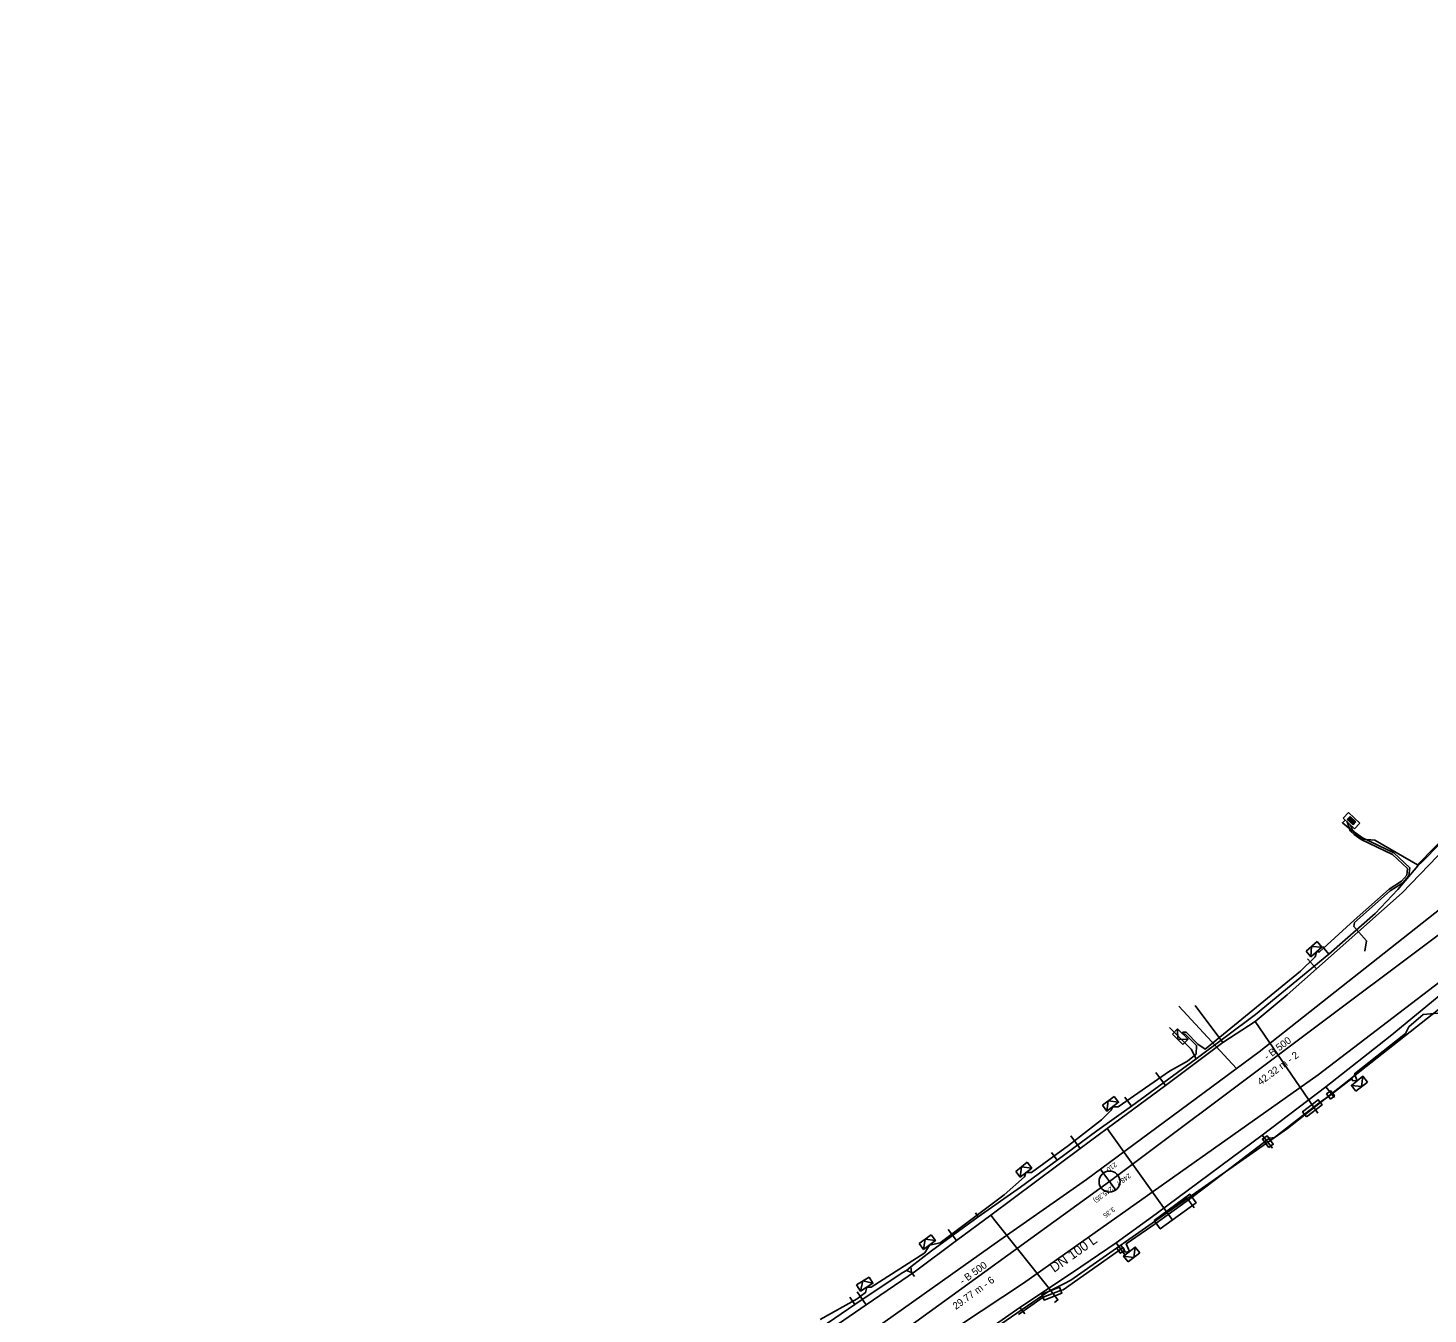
# Model space of a CAD drawing. Extents: x -600636 to -600148, y -1203980 to -1203569.
# Drawn here: x -600589.5 to -600456.1, y -1203740.1 to -1203617.6 of the extents above; entities that cross this region are included whole.
import ezdxf

# ---------------------------------------------------------------- set-up
doc = ezdxf.new("R2010")
doc.units = 0
for name, color, linetype in [('Cetin zam průběh', 7, 'Continuous'), ('EON objekty', 7, 'Continuous'), ('EON podzemní NN', 7, 'Continuous'), ('EON podzemní zrušené', 7, 'Continuous'), ('GasNet NTL', 7, 'Continuous'), ('Implicitní', 7, 'Continuous'), ('VaK Břeclav_kanalizace', 7, 'Continuous'), ('VaK Břeclav_kanalizace_popis', 7, 'Continuous'), ('Vak Břeclav_vodovod', 7, 'Continuous'), ('Vak Břeclav_vodovod_popis', 7, 'Continuous'), ('Vrstva 9', 7, 'Continuous')]:
    doc.layers.add(name, color=color, linetype=linetype)

# ---------------------------------------------------------------- blocks, each defined once
blk = doc.blocks.new('NN630')
at = {"layer": 'Vrstva 9'}
for points in [[(0, -0.7), (-0.7, 0)], [(-0.7, -0.7), (-0.7, 0), (0.7, 0), (0.7, -0.7)], [(-0.7, -0.7), (0.7, -0.7)], [(0, -0.7), (0.7, 0)]]:
    blk.add_lwpolyline(points, dxfattribs=at)
blk = doc.blocks.new('NN620')
at = {"layer": 'EON objekty'}
for points in [[(0.75, 0), (-0.75, 0)], [(-0.75, 0), (-0.75, -0.75)], [(0.75, -0.75), (0.75, 0)], [(-0.75, -0.75), (0.75, -0.75)], [(0.37, -0.18), (-0.38, -0.18)], [(-0.38, -0.18), (-0.38, -0.56)], [(-0.38, -0.56), (0.37, -0.56)], [(0.32, -0.23), (-0.33, -0.23)], [(-0.33, -0.23), (-0.33, -0.51)], [(-0.33, -0.51), (0.32, -0.51)], [(0.27, -0.27), (-0.28, -0.27)], [(-0.28, -0.27), (-0.28, -0.46)], [(-0.28, -0.46), (0.27, -0.46)], [(0.23, -0.32), (-0.23, -0.32)], [(-0.23, -0.32), (-0.23, -0.42)], [(-0.23, -0.42), (0.23, -0.42)], [(-0.19, -0.37), (0.19, -0.37)], [(0.23, -0.42), (0.23, -0.32)], [(0.27, -0.46), (0.27, -0.27)], [(0.32, -0.51), (0.32, -0.23)], [(0.37, -0.56), (0.37, -0.18)]]:
    blk.add_lwpolyline(points, dxfattribs=at)
blk = doc.blocks.new('MoSymbol 2')
at = {"layer": 'Implicitní'}
blk.add_line((0, 0.0005), (0, -0.00075), dxfattribs=at)
blk.add_circle((0, 0), 0.0005, dxfattribs=at)

msp = doc.modelspace()

# ---------------------------------------------------------------- linework, layer by layer
at = {"layer": 'Cetin zam průběh'}
for points in [[(-600456.63, -1203697.04), (-600445.32, -1203685.49)], [(-600456.63, -1203697.04), (-600457.08, -1203697.43), (-600458.99, -1203699.7), (-600461.15, -1203701.99), (-600465.55, -1203705.86), (-600472.55, -1203711.62), (-600478.19, -1203715.83), (-600484.38, -1203720.33), (-600487.67, -1203722.68), (-600491.45, -1203725.5), (-600494.94, -1203728.06), (-600498.99, -1203730.87), (-600503.43, -1203734.12), (-600505.38, -1203735.65)], [(-600465.55, -1203705.86), (-600461.15, -1203701.99), (-600458.99, -1203699.7), (-600457.08, -1203697.43), (-600456.63, -1203697.04)], [(-600466.17, -1203705.14), (-600465.55, -1203705.86)], [(-600478.19, -1203715.83), (-600472.55, -1203711.62), (-600465.55, -1203705.86)], [(-600490.14, -1203736.91), (-600480.27, -1203730.01), (-600469.5, -1203722.46), (-600453.01, -1203709.48)], [(-600465.84, -1203718.51), (-600459.73, -1203713.66), (-600454.7, -1203709.55)], [(-600480.74, -1203712.85), (-600478.67, -1203714.92), (-600478.19, -1203715.83)], [(-600484.38, -1203720.33), (-600478.19, -1203715.83)], [(-600471.92, -1203723.11), (-600465.84, -1203718.51)], [(-600465.84, -1203718.51), (-600465.03, -1203719.53)], [(-600485.01, -1203719.5), (-600484.38, -1203720.33)], [(-600491.45, -1203725.5), (-600487.67, -1203722.68), (-600484.38, -1203720.33)], [(-600485.84, -1203733.37), (-600482.03, -1203730.6), (-600480.91, -1203729.77), (-600471.92, -1203723.11)], [(-600471.92, -1203723.11), (-600470.93, -1203724.35)], [(-600498.99, -1203730.87), (-600494.94, -1203728.06), (-600491.45, -1203725.5)], [(-600491.98, -1203724.76), (-600491.45, -1203725.5)], [(-600505.4, -1203735.66), (-600505.38, -1203735.65), (-600503.43, -1203734.12), (-600498.99, -1203730.87)], [(-600499.24, -1203730.5), (-600498.99, -1203730.87)], [(-600482.03, -1203730.6), (-600480.91, -1203729.77)], [(-600495, -1203739.53), (-600490, -1203736.18), (-600485.84, -1203733.37)], [(-600485.84, -1203733.37), (-600485, -1203734.5)], [(-600506.23, -1203736.22), (-600505.79, -1203736)], [(-600505.4, -1203735.66), (-600505.79, -1203736)], [(-600505.79, -1203736), (-600505.33, -1203736.18)], [(-600505.33, -1203736.18), (-600505.4, -1203735.66)], [(-600505.33, -1203736.18), (-600505.04, -1203736.56)], [(-600506.23, -1203736.22), (-600510.74, -1203739.23), (-600519.05, -1203744.93), (-600519.22, -1203745.96), (-600520.6, -1203747.08), (-600523.03, -1203748.81), (-600529.84, -1203753.68), (-600533.39, -1203756), (-600537.76, -1203758.9), (-600542.81, -1203762.61), (-600547.1, -1203765.43), (-600552.78, -1203769.13), (-600553.37, -1203769.45), (-600553.89, -1203769.82), (-600554.42, -1203770.01), (-600558.01, -1203772.02)], [(-600499.06, -1203830.56), (-600501.19, -1203829.34), (-600520.52, -1203816.59), (-600528.18, -1203809.84), (-600537.51, -1203800.68), (-600551.58, -1203783.7), (-600551.71, -1203781.06), (-600528.73, -1203763.94), (-600503.65, -1203745.81), (-600492.34, -1203738.04), (-600490.82, -1203737.26)], [(-600510.74, -1203739.23), (-600506.23, -1203736.22)], [(-600490.82, -1203737.26), (-600490.14, -1203736.91)], [(-600511.2, -1203738.53), (-600510.74, -1203739.23)], [(-600551.61, -1203780.87), (-600546.02, -1203776.14), (-600534.46, -1203768.01), (-600525.37, -1203761.73), (-600517.43, -1203756.57), (-600515.95, -1203755.15), (-600506.94, -1203748.87), (-600505.47, -1203747), (-600500.48, -1203743.35), (-600495, -1203739.53)], [(-600520.6, -1203747.08), (-600519.22, -1203745.96), (-600519.05, -1203744.93), (-600510.74, -1203739.23)], [(-600495, -1203739.53), (-600494.53, -1203740.14)]]:
    msp.add_lwpolyline(points, dxfattribs=at)
at = {"layer": 'EON podzemní NN'}
for points in [[(-600464.01, -1203693.08), (-600464.27, -1203693.34), (-600462.36, -1203694.91), (-600461.18, -1203695), (-600457.12, -1203697.36), (-600445.42, -1203685.44)], [(-600463.82, -1203693.26), (-600463.52, -1203694.1), (-600463.14, -1203694.46), (-600462.48, -1203694.95), (-600459.49, -1203696.38), (-600458.07, -1203697.71), (-600458.14, -1203698.33), (-600458.64, -1203698.9), (-600459.83, -1203699.68), (-600463.16, -1203702.62), (-600466.45, -1203705.65), (-600466.74, -1203705.65), (-600466.87, -1203706.11), (-600468.26, -1203707.49), (-600477.36, -1203714.91), (-600478.04, -1203714.43), (-600479.17, -1203713.29), (-600479.47, -1203713.28), (-600479.47, -1203713.48), (-600479.26, -1203713.49), (-600478.18, -1203714.57), (-600478.22, -1203715.38), (-600479.03, -1203716.06), (-600480.75, -1203717.01), (-600485.65, -1203720.39), (-600486.16, -1203720.39), (-600486.3, -1203720.73), (-600487.22, -1203721.66), (-600490.37, -1203724.1), (-600493.9, -1203726.65), (-600494.42, -1203726.67), (-600494.55, -1203727.08), (-600496.51, -1203728.78), (-600502.6, -1203733.36), (-600503.61, -1203733.57), (-600504.07, -1203734.3), (-600509.16, -1203737.6), (-600509.59, -1203737.58), (-600509.7, -1203738.1), (-600510.52, -1203738.71), (-600514.04, -1203740.67)], [(-600455.19, -1203711.49), (-600456.59, -1203711.62), (-600457.93, -1203712.79), (-600458.27, -1203713.42), (-600463.11, -1203717.26), (-600462.87, -1203717.93), (-600463.31, -1203717.9), (-600463.37, -1203717.72), (-600465.2, -1203719.13), (-600465.6, -1203719.42), (-600466.39, -1203719.97), (-600467.88, -1203721.12), (-600470.75, -1203723.34), (-600471.23, -1203723.39), (-600476.5, -1203727.44), (-600478.6, -1203729.01), (-600482.01, -1203731.5), (-600484.88, -1203733.47), (-600484.56, -1203734.2), (-600484.97, -1203734.26), (-600485.17, -1203733.81), (-600485.61, -1203734.11), (-600490.89, -1203737.84), (-600491.12, -1203737.89), (-600492.79, -1203738.54), (-600495.12, -1203740.2)]]:
    msp.add_lwpolyline(points, dxfattribs=at)
for points in [[(-600467.7, -1203721.35), (-600468.06, -1203720.88), (-600466.58, -1203719.73), (-600466.21, -1203720.2)], [(-600465.42, -1203719.66), (-600465.78, -1203719.17), (-600465.38, -1203718.89), (-600465.03, -1203719.37)], [(-600471.29, -1203724.29), (-600471.89, -1203723.48), (-600471.45, -1203723.16), (-600470.86, -1203723.97)], [(-600482.21, -1203731.23), (-600478.82, -1203728.73), (-600478.22, -1203729.54), (-600481.62, -1203732.03)], [(-600485.78, -1203733.86), (-600485.38, -1203733.59), (-600485.04, -1203734.08), (-600485.44, -1203734.35)], [(-600492.9, -1203738.26), (-600491.23, -1203737.6), (-600491.01, -1203738.16), (-600492.69, -1203738.82)]]:
    msp.add_lwpolyline(points, close=True, dxfattribs=at)
at = {"layer": 'EON podzemní zrušené'}
msp.add_lwpolyline([(-600463.5, -1203693.56), (-600463.35, -1203693.99), (-600463.01, -1203694.31), (-600462.37, -1203694.78), (-600459.37, -1203696.21), (-600457.86, -1203697.64), (-600457.94, -1203698.41), (-600458.51, -1203699.05), (-600459.71, -1203699.84), (-600463.12, -1203702.85), (-600463.17, -1203703.23), (-600461.98, -1203704.59), (-600462.13, -1203705.57)], dxfattribs=at)
at = {"layer": 'GasNet NTL'}
for points in [[(-600376.52, -1203617.62), (-600381.81, -1203622.65), (-600388.25, -1203628.77), (-600399.65, -1203639.6), (-600410.04, -1203649.48), (-600410.35, -1203649.77), (-600417.47, -1203657.21), (-600420.27, -1203660.14), (-600432.74, -1203673.17), (-600439.94, -1203680.7), (-600445.87, -1203686.85), (-600458.57, -1203700.01), (-600466.75, -1203707.26), (-600469.55, -1203709.74), (-600472.59, -1203712.26), (-600475.67, -1203714.29), (-600481.14, -1203718.36), (-600486.68, -1203722.48)], [(-600467.59, -1203706.3), (-600466.75, -1203707.26)], [(-600478.29, -1203710.76), (-600475.67, -1203714.29)], [(-600472.59, -1203712.26), (-600466.6, -1203721)], [(-600482.06, -1203717.13), (-600481.14, -1203718.36)], [(-600486.68, -1203722.48), (-600489.25, -1203724.39), (-600497.78, -1203730.73), (-600501.03, -1203733.15), (-600504.95, -1203736.06), (-600509.64, -1203739.28), (-600520.2, -1203746.52), (-600535.72, -1203757.18), (-600536.81, -1203757.93), (-600541.8, -1203761.35), (-600546.79, -1203764.85), (-600559, -1203773.38), (-600566.88, -1203778.88), (-600575.24, -1203781.91), (-600588.36, -1203786.65), (-600589.51, -1203786.96)], [(-600486.68, -1203722.48), (-600480.99, -1203730.45)], [(-600490.16, -1203723.17), (-600489.25, -1203724.39)], [(-600478.4, -1203730.02), (-600479.1, -1203729.08), (-600480.99, -1203730.45)], [(-600497.78, -1203730.73), (-600497.35, -1203731.27), (-600492.35, -1203737.57), (-600491.38, -1203738.8), (-600491.7, -1203739.06)], [(-600480.99, -1203730.45), (-600480.43, -1203731.23)], [(-600501.82, -1203732.09), (-600501.03, -1203733.15)], [(-600510.5, -1203738.03), (-600509.64, -1203739.28)]]:
    msp.add_lwpolyline(points, dxfattribs=at)
at = {"layer": 'VaK Břeclav_kanalizace'}
for p, q in [((-600486.46, -1203727.53), (-600452.6, -1203702.14)), ((-600510.58, -1203744.98), (-600486.46, -1203727.53))]:
    msp.add_line(p, q, dxfattribs=at)
at = {"layer": 'Vak Břeclav_vodovod'}
msp.add_line((-600474.37, -1203716.76), (-600479.87, -1203710.82), dxfattribs=at)
for points in [[(-600454.25, -1203701.01), (-600472.2, -1203715.15), (-600488.66, -1203727.34), (-600496.91, -1203733.12), (-600525.43, -1203753.34), (-600551.89, -1203771.85), (-600568.7, -1203781.3)], [(-600529.07, -1203761.9), (-600506.65, -1203745.16), (-600494.67, -1203737.19), (-600466.59, -1203717.37), (-600450.01, -1203704.7)]]:
    msp.add_lwpolyline(points, dxfattribs=at)

# ---------------------------------------------------------------- block references
at = {"layer": 'EON podzemní NN'}
for name, p, rotation in [('NN620', (-600463.66, -1203693.41), 136.2722332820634), ('NN630', (-600466.74, -1203705.65), -138.44983611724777), ('NN630', (-600479.47, -1203713.48), -44.460425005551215), ('NN630', (-600462.87, -1203717.93), 38.28571111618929), ('NN630', (-600486.16, -1203720.39), -143.00993333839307), ('NN630', (-600494.42, -1203726.67), -141.69166107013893), ('NN630', (-600503.61, -1203733.57), -143.2847416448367), ('NN630', (-600484.56, -1203734.2), 37.45922774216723), ('NN630', (-600509.59, -1203737.59), -147.68895270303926)]:
    msp.add_blockref(name, p, dxfattribs=dict(at, rotation=rotation))
at = {"layer": 'VaK Břeclav_kanalizace', "xscale": 1999.7500312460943, "yscale": 1999.750031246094, "rotation": -143.63158106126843}
msp.add_blockref('MoSymbol 2', (-600486.46, -1203727.53), dxfattribs=at)

# ---------------------------------------------------------------- texts
at = {"layer": 'VaK Břeclav_kanalizace_popis'}
for s, height, rotation, p in [('- B 500', 0.682, 36.8631, (-600471.43, -1203715.98)), ('42.32 m - 2', 0.6824, 36.8631, (-600472.06, -1203718.39)), ('248,7  (245,35)', 0.4549, 216.3684, (-600484.62, -1203726.71)), ('210', 0.455, 216.3684, (-600485.96, -1203725.66)), ('3.35', 0.455, 216.3684, (-600486.14, -1203729.93)), ('- B 500', 0.682, 35.8737, (-600500.44, -1203737.36)), ('29.77 m - 6', 0.6824, 35.8737, (-600501.1, -1203739.76))]:
    msp.add_text(s, height=height, rotation=rotation, dxfattribs=at).set_placement(p)
at = {"layer": 'Vak Břeclav_vodovod_popis'}
msp.add_text('DN 100 L', height=0.91, rotation=35.2079, dxfattribs=at).set_placement((-600491.74, -1203736.23))

doc.saveas('drawing.dxf')
